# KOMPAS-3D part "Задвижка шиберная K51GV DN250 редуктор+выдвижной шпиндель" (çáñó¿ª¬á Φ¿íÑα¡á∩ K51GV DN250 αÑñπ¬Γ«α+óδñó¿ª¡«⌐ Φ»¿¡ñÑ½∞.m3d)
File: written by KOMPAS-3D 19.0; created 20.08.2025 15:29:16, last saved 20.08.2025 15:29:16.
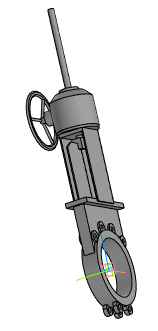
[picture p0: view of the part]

Document properties: Полное имя файла: Задвижка шиберная K51GV DN250 редуктор+выдвижной шпиндель.a3d

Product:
- Part/product: Задвижка шиберная K51GV DN250 редуктор+выдвижной шпиндель
    Масса: 82.9671

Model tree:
1. Операция без истории:1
